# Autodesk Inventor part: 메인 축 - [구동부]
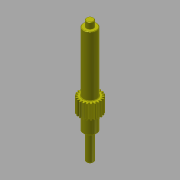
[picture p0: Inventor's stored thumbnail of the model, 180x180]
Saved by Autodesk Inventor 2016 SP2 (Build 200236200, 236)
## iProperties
Created: 2016-02
Part Number: 메인 축 - [구동부]
Material: 강철, 연강
Document SubType Name: Modeling
Categories: <?xml version="1.0" encoding="UTF-16"?> <MemberInstance><Categories><FamilyTemplate><FamilyTemplateParameter ValueType="xs:double" Id="1" ObjectReferenceKey="da
Density: 7.86 g/cm^3
Mass: 181.397 g
Surface Area: 79.0018 cm^2
Volume: 23.0784 cm^3
Appearance: 노란색
Author: mdu
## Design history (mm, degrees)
sketch "Sketch1"
  geometry: C1 r 12 at (0, 0)
  constraints: 1 centre point
  dimensions: "d0" = 24 diameter of C1 (= da_da)
extrude "Extrusion1" new body sketch "Sketch1" distance "d1" = 20 (= da_b); taper "d2" = 0 deg
workplane "Work Plane2"
feature "피치 지름" dims "d4" = 10, "d5" = 0
workplane "Work Plane8"
workplane "Work Plane9"
chamfer "모따기1" distance "d49" = 1; stored, may be unused: second distance "d50" = 2, angle "d51" = 45 deg
sketch "스케치3"
  geometry: C1 r 7.5 at (0, 0); 1 further point
  constraints: 1 centre point, 1 coincident
  dimensions: "d52" = 15 diameter of C1
extrude "돌출2" join sketch "스케치3" distance "d53" = 66; taper "d54" = 0 deg
sketch "스케치4"
  geometry: C1 r 4 at (0, 0); 1 further point
  constraints: 1 centre point, 1 coincident
  dimensions: "d55" = 8 diameter of C1
extrude "돌출3" join sketch "스케치4" distance "d56" = 7; taper "d57" = 0 deg
sketch "스케치5"
  geometry: C1 r 7.5 at (0, 0) reference; C2 r 7.5 at (0, 0) reference; 1 further point
extrude "돌출4" join sketch "스케치5" distance "d62" = 16; taper "d63" = 0 deg
sketch "스케치6"
  geometry: C1 r 4 at (0, 0); 1 further point
  constraints: 1 centre point, 1 coincident
  dimensions: "d64" = 8 diameter of C1
extrude "돌출5" join sketch "스케치6" distance "d65" = 30; taper "d66" = 0 deg
chamfer "모따기2" distance "d58" = 0.5; stored, may be unused: second distance "d59" = 2, angle "d60" = 45 deg
fillet "모깎기1" dims "d61" = 0.5
feature "스퍼 기어" dims "da_b" = 20, "da_d" = 22, "da_aw" = 31, "da_da" = 24, "da_df" = 19.5, "da_dw" = 22, angle "da_beta" = 0 deg, "da_lefttooth" = 0, "da_righttooth" = 0
sketch "스케치7" dims "d68" = 18
  geometry: C1 r 0.25 at (0, -9); 2 further points
  constraints: 2 vertical alignment, 1 centre point, 1 coincident, 2 other
  dimensions: "d67" = 0.5 diameter of C1
extrude "돌출6" join sketch "스케치7" distance "d69" = 0.3; taper "d70" = 0 deg
feature "면 이동1"
feature "면 이동2"
feature "면 이동3"
body "Solid1"
sketch "Sketch2"
  geometry: C1 r 12 at (0, 0) reference; C2 r 11 at (0, 0)
  constraints: 1 centre point, 1 coincident
  dimensions: "d3" = 22 diameter of C2 (= da_dw)
body "Srf1"
node "투영된 루프1"
other parameters: "d16" = 31 (= da_aw), "d17" = 0, "d34" = 1.428 (computed from da_z), "d39" = 0, "d41" = 0, "d43" = 31 (= da_aw), "d46" = 31 (= da_aw), "d47" = 0, "d48" = 0
